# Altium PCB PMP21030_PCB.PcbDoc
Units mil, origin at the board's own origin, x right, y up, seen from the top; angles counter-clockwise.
Board outline 3700 x 1800 mil, 2 copper layers (Top Layer, Bottom Layer), stack 62 mil thick; 65 components, 29 nets, 169 pads, 54 vias.
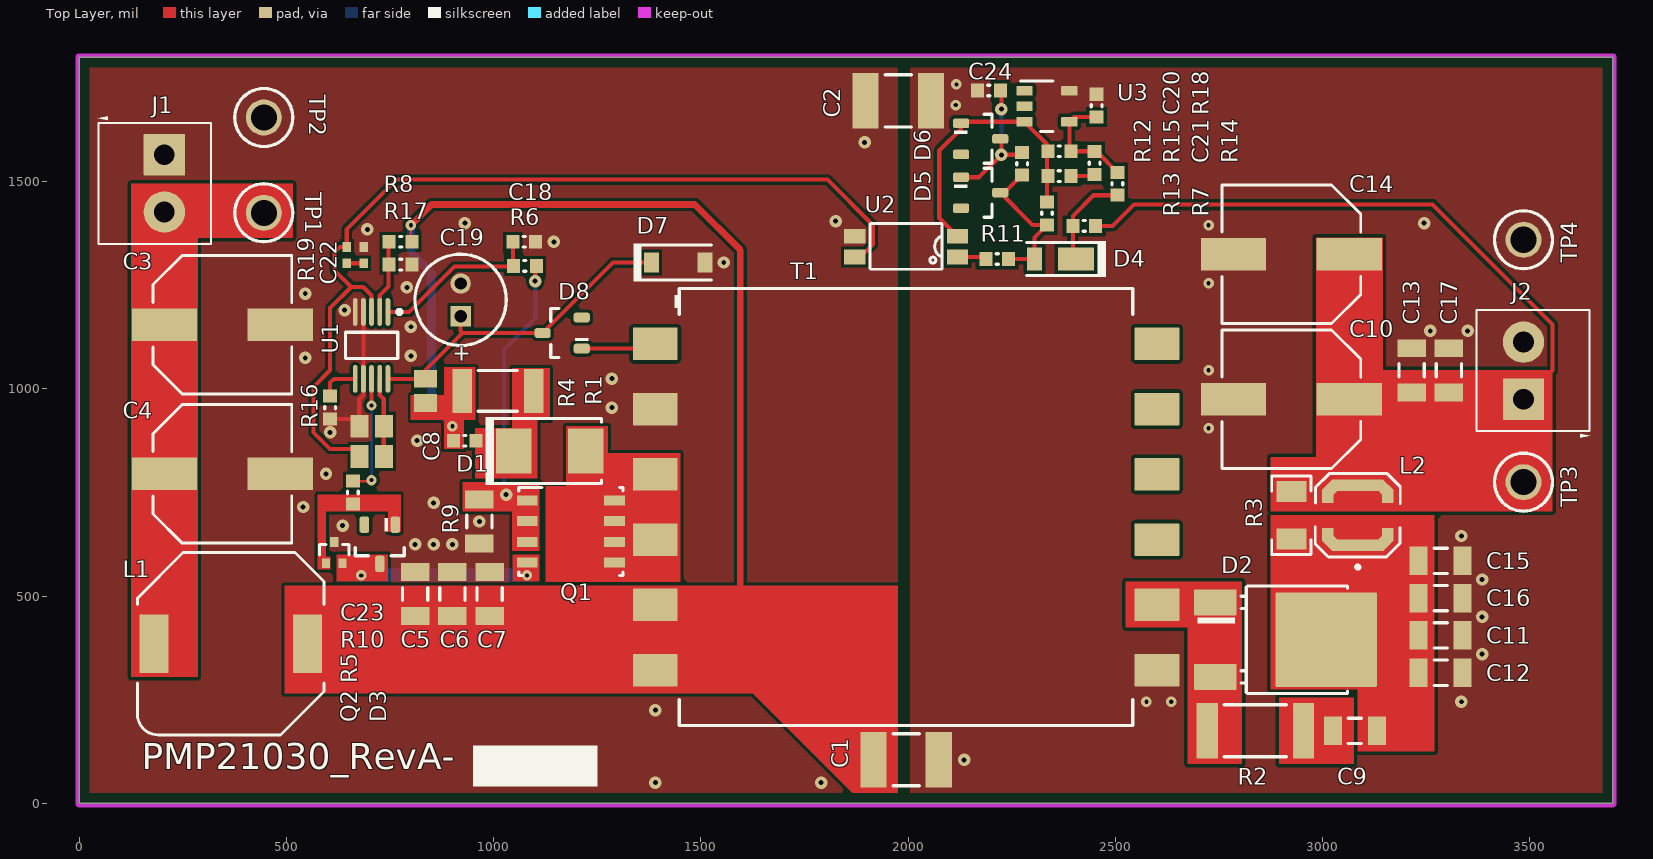
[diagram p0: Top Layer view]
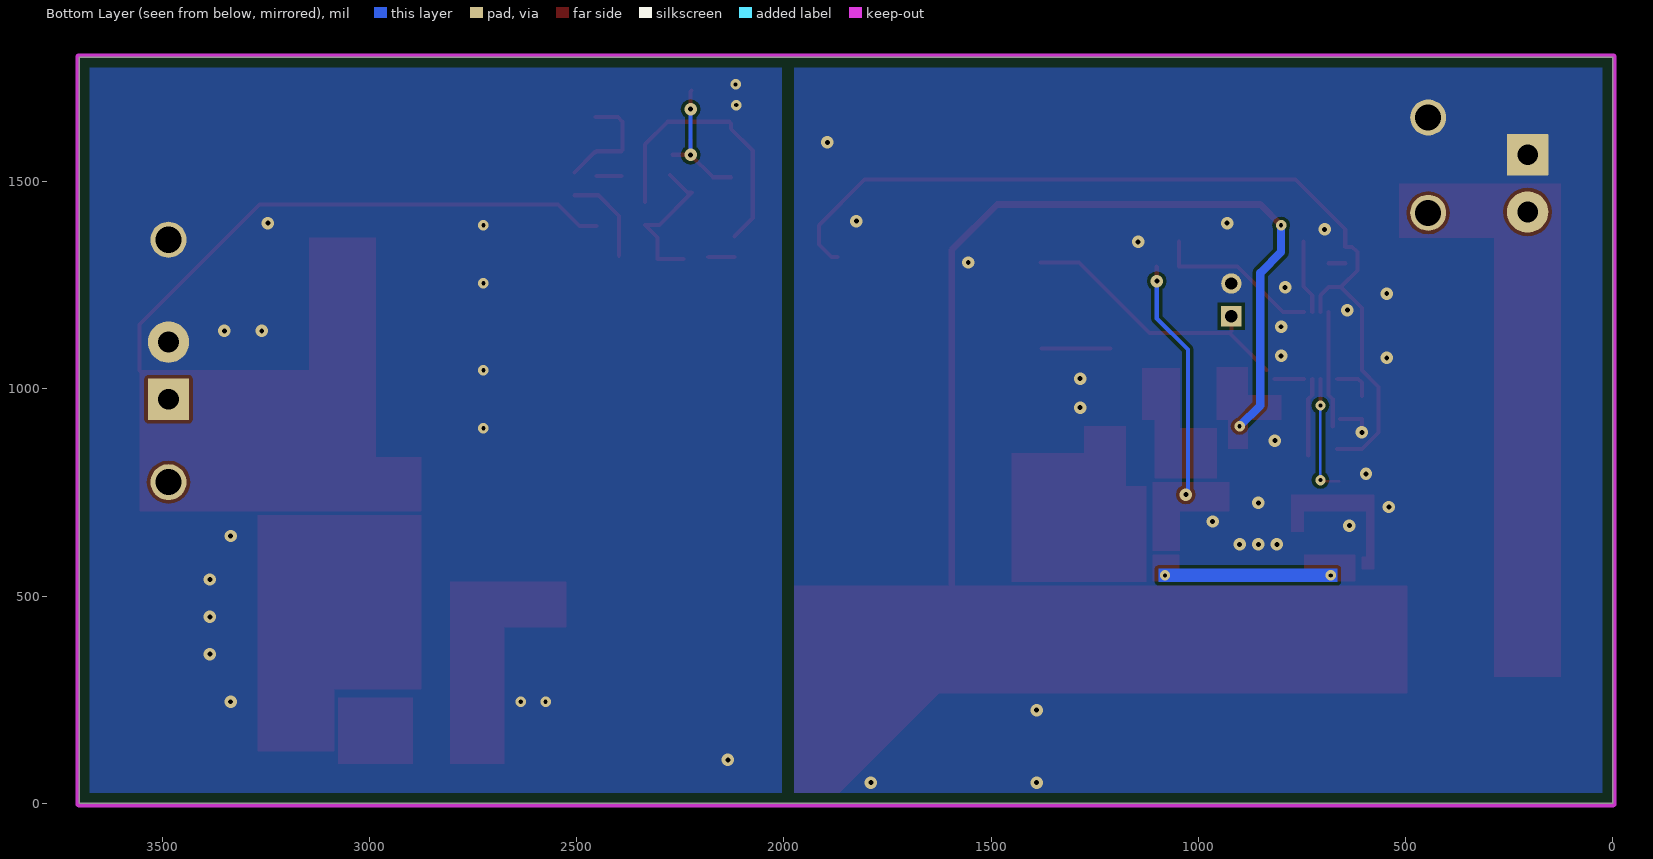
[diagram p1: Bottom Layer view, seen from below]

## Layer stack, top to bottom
Top Solder: solder mask 0.4, Solder Resist, Dk 3.5
Top Layer: signal copper 1.4
Dielectric1: core 59.2, FR-4, Dk 4.8
Bottom Layer: signal copper 1.4
Bottom Solder: solder mask 0.4, Solder Resist, Dk 3.5

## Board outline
0,0 3700,0 3700,1800 0,1800

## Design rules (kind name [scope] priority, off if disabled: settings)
AcuteAngle [All] p1: minimum=4.50000000000000E+0001 checktracksonly=FALSE
AssemblyTestPointUsage [All] p1: valid=2
BoardOutlineClearance BoardOutlineClearance_MountingHoles [OnCopper and InComponentClass('Mounting Holes')] p1: gap=25 ignorepadtopadclearanceinfootprint=FALSE
BoardOutlineClearance BoardOutlineClearance_Poly [OnCopper and InPoly] p2: gap=25 ignorepadtopadclearanceinfootprint=FALSE
BoardOutlineClearance [OnCopper and Not InComponentClass('Logo') and not InComponentClass('FiducialMark') and not InRegion(1000,500,4000,800)] p3: gap=25 ignorepadtopadclearanceinfootprint=FALSE
Clearance Clearance_Keepouts [((IsTrack Or IsArc) And Not InPoly) And IsFree and IsKeepOut vs ((IsTrack Or IsArc) And Not InPoly) And IsFree and IsKeepOut] p1: gap=10 ignorepadtopadclearanceinfootprint=FALSE
Clearance Clearance_Poly [InPolygon] p2: gap=8 ignorepadtopadclearanceinfootprint=FALSE except(0: Arc-Hole Track-Hole SMDPad-Hole THPad-Hole Via-Hole Fill-Hole Poly-Hole Region-Hole Text-Hole)
Clearance [All] p3: gap=7.87 ignorepadtopadclearanceinfootprint=FALSE except(0: Arc-Hole Track-Hole SMDPad-Hole THPad-Hole Via-Hole Fill-Hole Poly-Hole Region-Hole Text-Hole)
ComponentClearance ComponentClearance_MountingHoles_FiducialMarks [InComponentClass('Mounting Holes') vs InComponentClass('FiducialMark')] p1: gap=50 collisioncheckmode=3 verticalgap=10 showdistances=FALSE
ComponentClearance ComponentClearance_Shunt [InComponentClass('Header') vs InComponentClass('Shunt')] p2: gap=0 collisioncheckmode=3 verticalgap=0 showdistances=FALSE
ComponentClearance ComponentClearance_Logo [InComponentClass('Logo')] p3: gap=50 collisioncheckmode=3 verticalgap=10 showdistances=FALSE
ComponentClearance ComponentClearance_ScrewToNut [(HasFootprint('NY PMS 440 0025 PH')) vs (HasFootprint('Keystone_1902C'))] p4: gap=5 collisioncheckmode=3 verticalgap=10 showdistances=FALSE
ComponentClearance ComponentClearance_MountingHoles [InComponentClass('Mounting Holes')] p5: gap=250 collisioncheckmode=3 verticalgap=100000 showdistances=FALSE
ComponentClearance ComponentClearance_SmallPassives [HasFootprint('0201*') or HasFootprint('0402*') or HasFootprint('0508') or HasFootprint('0603*') or HasFootprint('0612') or HasFootprint('0805*') or HasFootprint('0815*') or HasFootprint('0830*') or HasFootprint('1206*') or HasFootprint('1210*') or HasFootprint('1808*') or HasFootprint('1812*') or HasFootprint('1825*') or HasFootprint('2010*') or HasFootprint('2220*') or HasFootprint('2225*') or HasFootprint('2512*') or HasFootprint('2728*') or HasFootprint('3518*') vs HasFootprint('0201*') or HasFootprint('0402*') or HasFootprint('0508') or HasFootprint('0603*') or HasFootprint('0612') or HasFootprint('0805*') or HasFootprint('0815*') or HasFootprint('0830*') or HasFootprint('1206*') or HasFootprint('1210*') or HasFootprint('1808*') or HasFootprint('1812*') or HasFootprint('1825*') or HasFootprint('2010*') or HasFootprint('2220*') or HasFootprint('2225*') or HasFootprint('2512*') or HasFootprint('2728*') or HasFootprint('3518*')] p6: gap=14.96 collisioncheckmode=3 verticalgap=10 showdistances=FALSE
ComponentClearance ComponentClearance_THtoSMT [IsThruComponent vs IsSMTComponent] p7: gap=15 collisioncheckmode=3 verticalgap=30 showdistances=FALSE
ComponentClearance ComponentClearance_THtoTH [IsThruComponent vs IsThruComponent] p8: gap=15 collisioncheckmode=3 verticalgap=30 showdistances=FALSE
ComponentClearance [All] p9: gap=15 collisioncheckmode=3 verticalgap=10 showdistances=FALSE
DiffPairsRouting [All] p1: maxlimit=100 minlimit=10 mostfreqgap=10 toplayer_minwidth=15 toplayer_maxwidth=15 toplayer_prefwidth=15 bottomlayer_minwidth=15 bottomlayer_maxwidth=15 bottomlayer_prefwidth=15 maxuncoupledlength=1000
FabricationTestPointUsage TestPointUsage [All] p1: valid=2 allowmultiple=FALSE
FabricationTestpoint Testpoint [All] p1: side=3 testpointundercomponent=TRUE minsize=40 maxsize=100 preferedsize=60 minholesize=0 maxholesize=40 preferedholesize=32 testpointgrid=1 allowsidetop=TRUE allowsidebottom=TRUE usegrid=TRUE gridtolerance=0.01
FanoutControl Fanout_LCC [IsLCC] p1: bgadir=Out bgaviamode=Centered fanoutstyle=Auto fanoutdirection=Alternating viagrid=1 // Fanout_LCC (Default Rule)
FanoutControl Fanout_BGA [IsBGA] p2: bgadir=Out bgaviamode=Centered fanoutstyle=Auto fanoutdirection=Alternating viagrid=1 // Fanout_BGA (Default Rule)
FanoutControl Fanout_Default [All] p4: bgadir=Out bgaviamode=Centered fanoutstyle=Auto fanoutdirection=Alternating viagrid=1 // Fanout_Default (Default Rule)
FanoutControl Fanout_Small [(CompPinCount < 5)] p5: bgadir=Out bgaviamode=Centered fanoutstyle=Auto fanoutdirection=OutThenIn viagrid=1 // Fanout_Small (Default Rule)
HoleSize [All] p1: absolutevalues=TRUE maxlimit=251 minlimit=7.87 maxpercent=80.000 minpercent=20.000
MinimumAnnularRing MinimumAnnularRing_ThermalPadVias [IsVia and InAnyComponent] p1: minimumring=5.91
MinimumAnnularRing [All] p2: minimumring=7
MinimumSolderMaskSliver MinimumSolderMaskSliver_Logo [InComponentClass('Logo') vs InComponentClass('Logo')] p1: minsoldermaskwidth=0.7
MinimumSolderMaskSliver [All] p2: minsoldermaskwidth=0.7
PlaneConnect [All] p1: planeconnectstyle=Direct reliefexpansion=10 reliefentries=4 reliefconductorwidth=10 reliefairgap=10
PolygonConnect [All] p1: connectstyle=Direct reliefconductorwidth=10 reliefentries=4 polygonreliefangle="90 Angle" airgapwidth=10
RoutingVias ThermalPadVias [IsVia and InAnyComponent] p1: holewidth=7.87 width=19.68 viastyle="Through Hole" minholewidth=7.87 minwidth=19.68 maxholewidth=12.99 maxwidth=23.62
RoutingVias [All] p2: holewidth=16 width=34 viastyle="Through Hole" minholewidth=7.87 minwidth=25 maxholewidth=40 maxwidth=65
SilkToBoardRegionClearance [Not ((IsComment or IsDesignator) And (Hide <> 'False')) and not InRegion(1000,500,4000,800)] p1:
SilkToSilkClearance SilkToSilkClearance_Pb-FreeLogo [(HasFootprint('Pb-Free_Overlay_Medium') OR HasFootprint('Pb-Free_Overlay_Small')) vs (HasFootprint('Pb-Free_Overlay_Medium') OR HasFootprint('Pb-Free_Overlay_Small'))] p1: silktosilkclearance=0
SilkToSilkClearance [All] p2: silktosilkclearance=4
SilkToSolderMaskClearance SilkToComponentPadClearance [IsPad and InAnycomponent] p1: minsilkscreentomaskgap=5 clearancetoexposedcopper=TRUE
SilkToSolderMaskClearance "Silk to Solder Mask Opening" [All] p2: minsilkscreentomaskgap=4 clearancetoexposedcopper=FALSE
SolderMaskExpansion [All] p1: expansion=1.97
Width [All] p1: maxlimit=100 minlimit=6 preferedwidth=10 checkconnectedcopper=TRUE
15 further rules are at their usual default settings.

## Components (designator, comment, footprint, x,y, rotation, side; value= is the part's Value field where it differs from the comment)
C1 "C4532X7R3D222K130KA" 1812 1995,105 r180 top value=2200pF
C2 "C4532X7R3D222K130KA" 1812 1976.26,1695 r180 top value=2200pF
C3 "EEE-FK1J470P" SM_RADIAL_F 345,1155 r0 top value=47uF
C4 "EEE-FK1J470P" SM_RADIAL_F 345,795 r0 top value=47uF
C5 "C3216X7S2A225K160AB" 1206l 810,505 r90 top value=2.2uF
C6 "C3216X7S2A225K160AB" 1206l 900,505 r90 top value=2.2uF
C7 "C3216X7S2A225K160AB" 1206l 990,505 r90 top value=2.2uF
C8 "GCJ188R72A104KA01D" 0603L 930,875 r0 top value=0.1uF
C9 "GRM31A7U2J221JW31D" 1206L 3077.91,175 r180 top value=220pF
C10 "EEE-FK1J470P" SM_RADIAL_F 2925,975 r180 top value=47uF
C11 "C3216X7S2A225K160AB" 1206l 3285,405 r0 top value=2.2uF
C12 "C3216X7S2A225K160AB" 1206l 3285,315 r0 top value=2.2uF
C13 "C3216X7S2A225K160AB" 1206l 3215,1045 r90 top value=2.2uF
C14 "EEE-FK1J470P" SM_RADIAL_F 2925,1325 r180 top value=47uF
C15 "C3216X7S2A225K160AB" 1206l 3285,585 r0 top value=2.2uF
C16 "C3216X7S2A225K160AB" 1206l 3285,495 r0 top value=2.2uF
C17 "GRM31CR72D104KW03L" 1206l 3305,1045 r90 top value=0.1uF
C18 "GRM1885C2A101JA01D" 0603L 1073.5,1355 r0 top value=100pF
C19 "EKMG101ELL1R0ME11D" Chemi-Con_500x1100 920,1215 r90 top value=1uF
C20 "GCM188R71H472KA37D" 0603L 2364.96,1573.5 r180 top value=4700pF
C21 "C1608X7R1E104K080AA" 0603L 2450,1545 r270 top value=0.1uF
C22 "GRM155R61E475ME15" 0402L 686,1323 r90 top value=4.7uF
C23 "GRM219R71E105KA88D" 0805L 705,910 r180 top value=1uF
C24 "GCM188R71E105KA64D" 0603L 2195,1720 r180 top value=1uF
D1 "ES2D-13-F" SMB 1135,850 r0 top value=200V
D2 "MURD320T4G" DPAK 2875,395 r0 top value=200V
D3 "BAS16LT1G" SOT-23 725,625 r270 top value=100V
D4 "DFLZ24-7" PowerDI123 2354.96,1313.5 r180 top value=24V
D5 "BAS16LT1G" SOT-23 2174.96,1473.5 r0 top value=100V
D6 "BAS16LT1G" SOT-23 2174.96,1603.5 r0 top value=100V
D7 "MMSZ4717T1G" SOD-123 1445,1305 r0 top value=43V
D8 "BAS16LT1G" SOT-23 1165,1135 r180 top value=100V
J1 "ED555/2DS" TERM_BLK_ED555-2DS 205,1565 r270 top
J2 "ED555/2DS" TERM_BLK_ED555-2DS 3485,975 r90 top
L1 "MSS1048-103MLB" MSS1048 365,385 r0 top value=10uH
L2 "LPS4018-332MLB" LPS4018 3085,695 r90 top value=3.3uH
Q1 "FDMS86200" TRANS_Fairchild_PQFN08A 1186,656 r0 top value=150V
Q2 "MMBT3906TT1G" SOT-416 615,605 r90 top value="40 V"
R1 "CRCW201051K0JNEF" 2010L 1010,995 r180 top value=51k
R2 "CRCW251251R0JNEG" 2512 2837.91,175 r0 top value=51
R3 "CRCW12061R00JNEA" 1206 2925,695 r90 top value=1.0
R4 "CRCW08052K00JNEA" 0805L 835,995 r270 top value=2.0k
R5 "CRCW06034R70JNEA" 0603L 660,750 r270 top value=4.7
R6 "CRCW06032K05FKEA" 0603L 1075,1297 r0 top value=2.05k
R7 "CRCW06030000Z0EA" 0603L 2424.96,1393.5 r0 top value=0
R8 "CRCW0603100KFKEA" 0603L 775,1355 r0 top value=100k
R9 "WSLP1206R0200FEA" 1206L 965,680 r90 top value=0.02
R10 "CRCW08054K70JNEA" 0805L 705,837 r180 top value=4.7k
R11 "CRCW06034K99FKEA" 0603L 2214.96,1313.5 r0 top value=4.99k
R12 "CRCW060310K0FKEA" 0603L 2274.96,1543.5 r270 top value=10.0k
R13 "CRCW060310K0FKEA" 0603L 2334.96,1423.5 r270 top value=10.0k
R14 "CRCW060349K9FKEA" 0603L 2505,1495 r270 top value=49.9k
R15 "CRCW060349K9FKEA" 0603L 2364.96,1513.5 r180 top value=49.9k
R16 "CRCW0603140KFKEA" 0603L 605,955 r270 top value=140k
R17 "CRCW06039K31FKEA" 0603L 775,1300 r180 top value=9.31k
R18 "CRCW06032K74FKEA" 0603L 2454.96,1683.5 r270 top value=2.74k
R19 "CRCW0402499RFKED" 0402L 645,1323 r90 top value=499
T1 "GA3136-BL" Coilcraft_GA3136-BL 1995,715 r0 top value=35uH
TP1 "5005" Keystone5005 445,1425 r90 top
TP2 "5006" Keystone5006 445,1655 r90 top
TP3 "5005" Keystone5005 3485,775 r90 top
TP4 "5006" Keystone5006 3485,1360 r90 top
U1 "LM3481MM/NOPB" MUB10A_N 705,1105 r270 top
U2 "TCMT1107" SOP-4 1994.96,1343.5 r180 top
U3 "TL431AIDBVRA" DBV0005A_N 2334.96,1682.01 r0 top

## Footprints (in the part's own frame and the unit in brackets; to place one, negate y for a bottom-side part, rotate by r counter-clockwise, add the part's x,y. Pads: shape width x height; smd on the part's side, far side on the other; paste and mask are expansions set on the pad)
0402L [mm] "0402 from SM-752 data"
  rect 0.6x0.5 smd: 1(-0.5,0) 2(0.5,0)
  body extent -0.55,-0.3 0.55,0.3, height 0.6
0603L [mm] "0603 from SM-752 data"
  rect 0.8x0.85 smd: 1(-0.7,0) 2(0.7,0)
  silkscreen extent -0.07,-0.33 0.07,0.33, body extent -0.87,-0.47 0.87,0.47, height 1
0805L [mm] "0805 from SM-752 data"
  rect 1.1x1.4 smd: 1(-0.75,0) 2(0.75,0)
  body extent -1.1,-0.72 1.1,0.72, height 1.45
1206 [mm] "1206 from SM-752 data"
  rect 1.3x1.85 smd: 1(-1.45,0) 2(1.45,0)
  silkscreen extent -2.4,-1.21 2.4,1.21, body extent -1.7,-0.9 1.7,0.9, height 1.35
1206l [mm] "1206 from SM-752 data"
  rect 1.1x1.75 smd: 1(-1.35,0) 2(1.35,0)
  silkscreen extent -0.4,-0.77 0.4,0.77, body extent -1.7,-0.9 1.7,0.9, height 1.35
1206L [mm] "1206 from SM-752 data"
  rect 1.1x1.75 smd: 1(-1.35,0) 2(1.35,0)
  silkscreen extent -0.4,-0.77 0.4,0.77, body extent -1.7,-0.9 1.7,0.9, height 1.35
1812 [mm]
  rect 1.6x3.4 smd: 1(-2,0) 2(2,0)
  silkscreen extent -0.8,-1.6 0.8,1.6, body extent -2.4,-1.7 2.4,1.7, height 1.35
2010L [mm]
  rect 1.2x2.7 smd: 1(-2.2,0) 2(2.2,0)
  silkscreen extent -1.2,-1.25 1.2,1.25, body extent -2.73,-1.45 2.73,1.45, height 1.66
2512 [mm] "Chip Resistor, Body 6.3x3.2mm, IPC Medium Density"
  rect 1.3x3.4 smd: 1(-2.95,0) 2(2.95,0)
  silkscreen extent -1.9,-1.6 1.9,1.6, body extent -3.22,-1.67 3.22,1.67, height 0.71
Chemi-Con_500x1100 [mm] "TH, 2-Leads, Dia 5mm, Lead Sapcing 2mm"
  rect 1.25x1.25 hole 0.75: 1(-1,0)
  round 1.25 hole 0.75: 2(1,0)
  silkscreen extent -2.8,-2.8 2.8,2.8, body extent -2.75,-2.75 2.75,2.75, height 12.5
Coilcraft_GA3136-BL [mm] "SMD, 12-Leads, Body 26x26.75mm"
  rrect5% 2.75x2 smd: 1(-15.375,10) 2(-15.375,6) 3(-15.375,2) 4(-15.375,-2) 5(-15.375,-6) 6(-15.375,-10) 7(15.375,-10) 8(15.375,-6) 9(15.375,-2) 10(15.375,2) 11(15.375,6) 12(15.375,10)
  silkscreen extent -14.2,-13.4 13.9,13.4, body extent -16.33,-13.38 16.33,13.37, height 14
DBV0005A_N [mm] "SOT23, 5-Leads, Body 2.9x1.6mm, Pitch 0.95mm, Lead Span 2.8mm, IPC Medium Density"
  rrect17% 1x0.6 smd: 1(-1.375,0.95) 2(-1.375,0) 3(-1.375,-0.95) 4(1.375,-0.95) 5(1.375,0.95)
  silkscreen extent -1.63,-1.55 0.38,1.55, body extent -1.42,-1.46 1.42,1.46, height 1.09
DPAK [mm] "D-PAK, 3-Pads, Body 6.22x6.73mm (max), TO-252AA using nominal STEP model"
  rrect6% 2.6x1.6 smd: 1(-3.4,2.28) 3(-3.4,-2.28)
  rrect2% 6.2x5.8 smd paste-2.9: 4(3.4,0)
  silkscreen extent -4.5,-3.3 4.7,3.28, body extent -3.86,-3.29 5.84,3.29, height 2.48
Keystone5005 [mil] "Keystone Compact loops"
  round 87 hole 63: 1(0,0)
  silkscreen extent -70,-70 70,70, body extent -63,-63 62,63, height 225
Keystone5006 [mil] "Keystone Compact loops"
  round 87 hole 63: 1(0,0)
  silkscreen extent -70,-70 70,70, body extent -63,-63 62,63, height 225
LPS4018 [mil]
  rect 28x123 smd: 1(-72.5,0) 2(72.5,0)
  rect 35.5x28 smd rot 45: 1(-64,64) 2(64.5,-63.5)
  rect 35.5x28 smd rot 135: 1(-64,-64) 2(64,64)
  rect 31.5x28 smd: 1(-46,72.5) 1(-46,-72.5) 2(46,72.5) 2(46,-72.5)
  silkscreen extent -129,-102 100,102, body extent -81,-81 81,81, height 71
MSS1048 [mm] "Coilcraft recommended land pattern Document 462-2 Revised 06/09/09"
  rect 1.78x3.56 smd: 1(-4.7,0) 2(4.7,0)
  silkscreen extent -5.71,-5.59 5.71,5.59, body extent -5.15,-5.1 5.15,5.1, height 5.12
MUB10A_N [mm] "TSSOP, 10-Leads, Body 3x3mm, Pitch 0.5mm, IPC Medium Density"
  oval 1.7x0.3 smd: 1(-2.05,1) 2(-2.05,0.5) 3(-2.05,0) 4(-2.05,-0.5) 5(-2.05,-1) 6(2.05,-1) 7(2.05,-0.5) 8(2.05,0) 9(2.05,0.5) 10(2.05,1)
  silkscreen extent -2.17,-1.6 0.8,1.83, body extent -1.6,-1.6 1.6,1.6, height 1.09
PowerDI123 [mm] "Diodes Inc recommended land pattern, document number DS30628 Rev. 6-2"
  rect 2.2x1.4 smd: 1(-1.275,0)
  rect 0.9x1.4 smd: 2(1.275,0)
  silkscreen extent -3.1,-1.09 1.76,1.09, body extent -2.38,-0.97 1.52,0.96, height 1
SM_RADIAL_F [mm] "8 x 10.2mm:  Panasonic F"
  rect 4x2 smd: 1(-3.55,0) 2(3.55,0)
  silkscreen extent -4.25,-4.25 4.25,4.25, body extent -4.25,-4.25 4.25,4.25, height 10.5
SMB [mil] "Molded Diode, 2-Leads, Body 5.4x3.6mm, IPC Medium Density, based on OnSemi component dimensions"
  rect 85x107.99 smd: 1(-87.01,0) 2(87.01,0)
  silkscreen extent -155,-82 125,82, body extent -106,-71 106,71, height 91
SOD-123 [mm] "On Semi recommended land pattern"
  rect 0.915x1.22 smd: 1(-1.637,0) 2(1.637,0)
  silkscreen extent -2.74,-1.17 2.03,1.17, body extent -1.93,-0.9 1.93,0.9, height 1.35
SOP-4 [mm] "Vishay Half Pitch Mini-Flat Package"
  rect 1.3x0.9 smd: 1(-3.15,0.635) 2(-3.15,-0.635) 3(3.15,-0.635) 4(3.15,0.635)
  silkscreen extent -2.2,-1.41 2.2,1.39, body extent -3.5,-1.4 3.5,1.4, height 2.12
SOT-23 [mm] "SOT23, 3-Leads, Body 2.9x1.3mm, Pitch 0.95mm, Lead Span 2.5mm, IPC Medium Density"
  rrect50% 1x0.6 smd: 1(-1.2,0.95) 2(-1.2,-0.95) 3(1.2,0)
  silkscreen extent -1.63,-1.5 0.7,1.5, body extent -1.16,-1.45 1.21,1.45, height 1
SOT-416 [mm] "NXP recommended footprint."
  rect 0.6x0.5 smd: 1(-0.65,0.5) 2(-0.65,-0.5) 3(0.65,0)
  silkscreen extent -0.13,-0.9 0.5,0.9, body extent -0.8,-0.9 0.8,0.9, height 0.82
TERM_BLK_ED555-2DS [mil]
  rrect4% 100x100 hole 50: 1(0,0)
  round 100 hole 50: 2(138,0)
  silkscreen extent -93,-161 215,113, body extent -69,-150 207,106, height 323
TRANS_Fairchild_PQFN08A [mm] "Fairchild PQFN08A recommended land pattern"
  rect 1.27x0.61 smd: 1(-2.67,1.905) 2(-2.67,0.635) 3(-2.67,-0.635) 4(-2.67,-1.905) 5(2.67,-1.905) 6(2.67,-0.635) 7(2.67,0.635) 8(2.67,1.905)
  Top Layer region: -1.215,-2.55 2.535,-2.55 2.535,2.55 -1.215,2.55
  silkscreen extent -3.2,-2.7 3.2,2.7, body extent -3.05,-2.55 3.05,2.55, height 1.11

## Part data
C1 C2: "CAP, CERM, 2200 pF, 2000 V,+/- 10%, X7R, 1812", Cap_Case=1812, Manufacturer=TDK, Supplier Part Number 1=445-2389-1-ND, TempCo=X7R, Tolerance_%=10, Value2=2000V, ValueDisplayed=2200pF
C3 C4 C10 C14: "CAP, AL, 47 µF, 63 V, +/- 20%, 0.65 ohm, AEC-Q200 Grade 2, SMD", Cap_Case=F, Manufacturer=Panasonic, Supplier Part Number 1=PCE3823CT-ND, Tolerance_%=20, Value1="0.65 ohm", Value2=63V, ValueDisplayed=47µF
C5 C6 C7 C11 C12 C13 C15 C16: "CAP, CERM, 2.2 µF, 100 V,+/- 10%, X7S, 1206", Cap_Case=1206, Manufacturer=TDK, Supplier Part Number 1=445-5207-1-ND, TempCo=X7S, Tolerance_%=10, Value1="0.005718 ohm", Value2=100V, ValueDisplayed=2.2µF
C8: "CAP, CERM, 0.1 µF, 100 V,+/- 10%, X7R, AEC-Q200 Grade 1, 0603", Cap_Case=0603, Manufacturer=MuRata, Supplier Part Number 1=490-13420-1-ND, TempCo=X7R, Tolerance_%=10, Value2=100V, ValueDisplayed=0.1µF
C9: "CAP, CERM, 220 pF, 630 V,+/- 5%, U2J, 1206", Cap_Case=1206, Manufacturer=MuRata, Supplier Part Number 1=490-4292-1-ND, TempCo=U2J, Tolerance_%=5, Value2=630V, ValueDisplayed=220pF
C17: "CAP, CERM, 0.1 µF, 200 V,+/- 10%, X7R, 1206", Cap_Case=1206, Manufacturer=MuRata, Supplier Part Number 1=490-13379-1-ND, TempCo=X7R, Tolerance_%=10, Value2=200V, ValueDisplayed=0.1µF
C18: "CAP, CERM, 100 pF, 100 V,+/- 5%, C0G/NP0, 0603", Cap_Case=0603, Manufacturer=MuRata, Supplier Part Number 1=490-1351-1-ND, TempCo=C0G/NP0, Tolerance_%=5, Value2=100V, ValueDisplayed=100pF
C19: "CAP, AL, 1 µF, 100 V, +/- 20%, TH", Cap_Case=5x11mm, Manufacturer=Chemi-Con, Supplier Part Number 1=565-1360-ND, Tolerance_%=20, Value2=100V, ValueDisplayed=1µF
C20: "CAP, CERM, 4700 pF, 50 V,+/- 10%, X7R, AEC-Q200 Grade 1, 0603", Cap_Case=0603, Manufacturer=MuRata, Supplier Part Number 1=490-4932-1-ND, TempCo=X7R, Tolerance_%=10, Value2=50V, ValueDisplayed=4700pF
C21: "CAP, CERM, 0.1 µF, 25 V,+/- 10%, X7R, 0603", Cap_Case=0603, Manufacturer=TDK, Supplier Part Number 1=445-1316-1-ND, TempCo=X7R, Tolerance_%=10, Value2=25V, ValueDisplayed=0.1µF
C22: "CAP, CERM, 4.7 µF, 25 V,+/- 20%, X5R, 0402", Cap_Case=0402, Manufacturer=MuRata, TempCo=X5R, Tolerance_%=20, Value2=25V, ValueDisplayed=4.7µF
C23: "CAP, CERM, 1 µF, 25 V,+/- 10%, X7R, 0805", Cap_Case=0805, Manufacturer=MuRata, Supplier Part Number 1=GRM219R71E105KA88D-ND, TempCo=X7R, Tolerance_%=10, Value2=25V, ValueDisplayed=1µF
C24: "CAP, CERM, 1 µF, 25 V,+/- 10%, X7R, AEC-Q200 Grade 1, 0603", Cap_Case=0603, Manufacturer=MuRata, Supplier Part Number 1=490-10673-1-ND, TempCo=X7R, Tolerance_%=10, Value2=25V, ValueDisplayed=1µF
D1: "Diode, Ultrafast, 200 V, 2 A, SMB", Manufacturer="Diodes Inc.", Supplier Part Number 1=ES2D-FDICT-ND, Value1=2A, Value2=0.92V
D2: library part CMP-0074782-1, "Diode, Ultrafast, 200 V, 3 A, AEC-Q101, DPAK", Manufacturer="ON Semiconductor", Supplier Part Number 1=MURD320T4GOSCT-ND, Value1=3A, Value2=0.95V
D3 D5 D6 D8: "Diode, Switching, 100 V, 0.2 A, SOT-23", Manufacturer="ON Semiconductor", Supplier Part Number 1=BAS16LT1GOSCT-ND, Value1=0.2A, Value2=1.25V
D4: "Diode, Zener, 24 V, 1 W, PowerDI123", Manufacturer="Diodes Inc.", Power_W=1, Supplier Part Number 1=DFLZ24DICT-ND, Value1=1W
D7: library part CMP-0005748-2, "Diode, Zener, 43 V, 500 mW, SOD-123", Manufacturer="ON Semiconductor", Power_W=500mW, Supplier Part Number 1=MMSZ4717T1GOSCT-ND, Value1=0.5W
J1 J2: "Terminal Block, 3.5mm Pitch, 2x1, TH", Color=Grey, Current_A=6, Manufacturer="On-Shore Technology", Supplier Part Number 1=ED1514-ND, Voltage_V=150
L1: "Inductor, Shielded Drum Core, Ferrite, 10 µH, 4.32 A, 0.03 ohm, SMD", Manufacturer=Coilcraft, Value1="0.03 ohm", Value2=4.32A, ValueDisplayed=10µH
L2: "Inductor, Shielded Drum Core, Ferrite, 3.3 µH, 1.9 A, 0.08 ohm, SMD", Manufacturer=Coilcraft, Value1="0.08 ohm", Value2=1.9A, ValueDisplayed=3.3µH
Q1: "MOSFET, N-CH, 150 V, 35 A, PQFN08A", Alternate Manufacturer=None, Manufacturer="Fairchild Semiconductor", Supplier Part Number 1=FDMS86200CT-ND, Value1="? ohm", Value2="33 nC"
Q2: library part "MMBT3906TT1G, ON Semiconductor", "Transistor, PNP, 40 V, 0.2 A, SOT-416", Manufacturer="ON Semiconductor", Supplier Part Number 1=MMBT3906TT1GOSCT-ND, Value1="0.2 A", Value2=300
R1: "RES, 51 k, 5%, 0.75 W, AEC-Q200 Grade 0, 2010", Manufacturer=Vishay-Dale, Power_W=0.75, Supplier Part Number 1=541-51KWCT-ND, TempCo="200 ppm/C", Tolerance_%=5, Value1=5%, Value2=0.75W, Value_Code=51k0, ValueDisplayed=51k
R2: "RES, 51, 5%, 1 W, AEC-Q200 Grade 0, 2512", Manufacturer=Vishay-Dale, Power_W=1, Supplier Part Number 1=541-51XCT-ND, TempCo="200 ppm/C", Tolerance_%=5, Value1=5%, Value2=1W, Value_Code=51R0, ValueDisplayed=51
R3: "RES, 1.0, 5%, 0.25 W, 1206", Manufacturer=Vishay-Dale, Power_W=0.25, Supplier Part Number 1=541-1.0ECT-ND, TempCo="200 ppm/C", Tolerance_%=5, Value1=5%, Value2=0.25W, Value_Code=1R00, ValueDisplayed=1.0
R4: "RES, 2.0 k, 5%, 0.125 W, 0805", Manufacturer=Vishay-Dale, Power_W=0.125, Supplier Part Number 1=541-2.0KACT-ND, TempCo="200 ppm/C", Tolerance_%=5, Value1=5%, Value2=0.125W, Value_Code=2k00, ValueDisplayed=2.0k
R5: "RES, 4.7, 5%, 0.1 W, 0603", Manufacturer=Vishay-Dale, Power_W=0.1, Supplier Part Number 1=541-4.7GCT-ND, TempCo="200 ppm/C", Tolerance_%=5, Value1=5%, Value2=0.1W, Value_Code=4R70, ValueDisplayed=4.7
R6: "RES, 2.05 k, 1%, 0.1 W, 0603", Manufacturer=Vishay-Dale, Power_W=0.1, Supplier Part Number 1=541-2.05KHCT-ND, TempCo="100 ppm/C", Tolerance_%=1, Value1=1%, Value2=0.1W, Value_Code=2k05, ValueDisplayed=2.05k
R7: "RES, 0, 5%, 0.1 W, 0603", Manufacturer=Vishay-Dale, Power_W=0.1, Supplier Part Number 1=541-0.0GCT-ND, TempCo="200 ppm/C", Tolerance_%=5, Value1=5%, Value2=0.1W, Value_Code=0000, ValueDisplayed=0
R8: "RES, 100 k, 1%, 0.1 W, 0603", Manufacturer=Vishay-Dale, Power_W=0.1, Supplier Part Number 1=541-100KHCT-ND, TempCo="100 ppm/C", Tolerance_%=1, Value1=1%, Value2=0.1W, Value_Code=100k
R9: "RES, 0.02, 1%, 1 W, 1206", Manufacturer=Vishay-Dale, Power_W=1, Supplier Part Number 1=WSLP-.02CT-ND, TempCo="75 ppm/C", Value1=1%, Value2=1W, Value_Code=R020, ValueDisplayed=0.02
R10: "RES, 4.7 k, 5%, 0.125 W, 0805", Manufacturer=Vishay-Dale, Power_W=0.125, Supplier Part Number 1=541-4.7KACT-ND, TempCo="200 ppm/C", Tolerance_%=5, Value1=5%, Value2=0.125W, Value_Code=4k70, ValueDisplayed=4.7k
R11: "RES, 4.99 k, 1%, 0.1 W, 0603", Manufacturer=Vishay-Dale, Power_W=0.1, Supplier Part Number 1=541-4.99KHCT-ND, TempCo="100 ppm/C", Tolerance_%=1, Value1=1%, Value2=0.1W, Value_Code=4k99, ValueDisplayed=4.99k
R12 R13: "RES, 10.0 k, 1%, 0.1 W, 0603", Manufacturer=Vishay-Dale, Power_W=0.1, Supplier Part Number 1=541-10.0KHCT-ND, TempCo="100 ppm/C", Tolerance_%=1, Value1=1%, Value2=0.1W, Value_Code=10k0, ValueDisplayed=10.0k
R14 R15: "RES, 49.9 k, 1%, 0.1 W, 0603", Manufacturer=Vishay-Dale, Power_W=0.1, Supplier Part Number 1=541-49.9KHCT-ND, TempCo="100 ppm/C", Tolerance_%=1, Value1=1%, Value2=0.1W, Value_Code=49k9, ValueDisplayed=49.9k
R16: "RES, 140 k, 1%, 0.1 W, 0603", Manufacturer=Vishay-Dale, Power_W=0.1, Supplier Part Number 1=541-140KHCT-ND, TempCo="100 ppm/C", Tolerance_%=1, Value1=1%, Value2=0.1W, Value_Code=140k
R17: "RES, 9.31 k, 1%, 0.1 W, 0603", Manufacturer=Vishay-Dale, Power_W=0.1, Supplier Part Number 1=541-9.31KHCT-ND, TempCo="100 ppm/C", Tolerance_%=1, Value1=1%, Value2=0.1W, Value_Code=9k31, ValueDisplayed=9.31k
R18: "RES, 2.74 k, 1%, 0.1 W, 0603", Manufacturer=Vishay-Dale, Power_W=0.1, Supplier Part Number 1=541-2.74KHCT-ND, TempCo="100 ppm/C", Tolerance_%=1, Value1=1%, Value2=0.1W, Value_Code=2k74, ValueDisplayed=2.74k
R19: "RES, 499, 1%, 0.063 W, 0402", Manufacturer=Vishay-Dale, Power_W=0.063, Supplier Part Number 1=541-499LCT-ND, TempCo="100 ppm/C", Tolerance_%=1, Value1=1%, Value2=0.063W, Value_Code=499R, ValueDisplayed=499
T1: library part CMP-0074777-1, "Transformer, Flyback, 35 uH, SMD", Manufacturer=Coilcraft, Supplier Part Number 1=994-GA3136-BL, ValueDisplayed=35µH
TP1 TP3: library part CMP-0055142-1, "Test Point, Compact, Red, TH", Color=Red, Manufacturer=Keystone, Supplier Part Number 1=36-5005-ND
TP2 TP4: "Test Point, Compact, Black, TH", Color=Black, Manufacturer=Keystone, Supplier Part Number 1=36-5006-ND
U1: "High Efficiency Low-Side N-Channel Controller for Switching Regulators, 10-pin MSOP, Pb-Free", Manufacturer="Texas Instruments", PackageTopMarking=ZXTT*SJPB, PowerWise=N, Supplier Part Number 1=LM3481MMTR-ND
U2: "Optocoupler, 3.75 kV, 80-160% CTR, SMT", Manufacturer=Vishay-Semiconductor, Supplier Part Number 1=TCMT1107CT-ND, Voltage_Isolation_Vrms=3750V
U3: library part TL431AIDBVR, "Adjustable Precision Shunt Regulator, 34 ppm / degC, 100 mA, -40 to 85 degC, 5-pin SOT-23 (DBV), Green (RoHS & no Sb/Br)", Alternate Manufacturer="Texas Instruments", Alternate PartNumber=Equivalent, Rating=Catalog, Supplier Part Number 1=296-15237-2-ND, Temp Coeff(Max)(ppm/ degree C)=92, Temp Coeff(Typ)(ppm/ degree C)=34

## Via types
v1: diameter 30, hole 12, Top Layer to Bottom Layer, tented both sides, 38 vias
v2: diameter 25, hole 10, Top Layer to Bottom Layer, tented both sides, 14 vias
v3: diameter 30, hole 12, Top Layer to Bottom Layer, 2 vias

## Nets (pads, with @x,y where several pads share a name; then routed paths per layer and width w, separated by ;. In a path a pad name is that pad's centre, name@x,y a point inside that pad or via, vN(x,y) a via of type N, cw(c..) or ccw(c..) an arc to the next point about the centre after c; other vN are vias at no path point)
GND: C1.1 C2.1 C10.2 C11.2 C12.2 C13.2 C14.2 C15.2 C16.2 C17.2 C24.2 J2.2 R18.1 T1.7 TP4.1 U3.5
  other v1: 2135,105 3335,245 3385,360 3385,450 3385,540 3335,645 3260,1140 3350,1140 3245,1400
  other v2: 2575,245 2635,245 2725,905 2725,1045 2725,1255 2725,1395 2115,1685 2116.26,1735
NetC1_2: C1.2 C5.1 C6.1 C7.1 C8.1 L1.2 R1.2 R4.2 R8.2 T1.5 T1.6 | length 2489.7
  Top Layer w6: v2(800,1395) 800,1356.06 R8.2@801.06,1355
  Top Layer w16: v2(800,1395) 850,1445 1485,1445 1595,1335 1595,478.78 T1.5
  Bottom Layer w20: v2(800,1395) 800,1330 850,1280 850,960 v2(900,910)
NetC3_1: C3.1 C4.1 J1.2 L1.1 TP1.1
NetC8_2: C8.2 D1.1 R1.1
NetC9_1: C9.1 C11.1 C12.1 C15.1 C16.1 D2.4 L2.1 R3.1
NetC9_2: C9.2 R2.2
NetC10_1: C10.1 C13.1 C14.1 C17.1 J2.1 L2.2 R3.2 R7.2 TP3.1 | length 1452.9
  Top Layer w10: R7.2 2493.5,1393.5 2545,1445 3265,1445 3555,1155 3555,1045 J2.1
NetC18_1: C18.1 R6.1 U1.1 | length 406.8
  Top Layer w10: U1.1 795.71,1185.71 905,1295 1045.94,1295 C18.1
NetC19_1: C19.1 D7.1 D8.3 R4.1 U1.10 | length 766.7
  Top Layer w10: U1.10 R4.1@815.71,1024.29 ; R4.1@835,1045.63 924.37,1135 ; C19.1 920,1139.37 924.37,1135 ; D7.1 1287.76,1305 D8.3 924.37,1135
NetC20_1: C20.1 C21.1 R14.1 R18.2 U3.4 | length 276.7
  Top Layer w10: R18.2 2400.44,1655.95 U3.4 2389.1,1576.93 C20.1 2452.52,1573.5 2454.96,1571.06 2456.5,1571.06 R14.1
NetC20_2: C20.2 D6.1 R13.1 R15.2 U2.2 U3.3 | length 677.8
  Top Layer w10: U2.2 2075,1412.48 2075,1575 2127.72,1627.72 D6.1 ; D6.1@2131.42,1644.61 U3.3 2334.96,1590.47 R13.1
NetC21_2: C21.2 R15.1 | length 60
  Top Layer w10: R15.1 C21.2@2452.52,1513.5
NetC22_1: C22.1 R19.1 | length 41
  Top Layer w10: R19.1 C22.1
NetC23_1: C23.1 R10.1 U1.9 | length 188.4
  Top Layer w10: U1.9 724.69,985.53 734.53,975.69 C23.1 R10.1@734.53,840
NetC24_1: C24.1 D5.1 D6.3 R12.1 | length 355.3
  Top Layer w10: D5.1 2170.91,1510.91 v1(2225,1565) ; C24.1 2225,1717.56 v3(2225,1675) ; D6.3@2225,1600.71 v1(2225,1565) ; R12.1@2268.9,1565 v1(2225,1565)
  Bottom Layer w10: v1(2225,1565) v3(2225,1675)
NetD1_2: D1.2 Q1.5 Q1.6 Q1.7 Q1.8 T1.3 T1.4
NetD2_1: D2.1 D2.3 R2.1 T1.8 | length 393.3
  Top Layer w10: T1.8 2735.16,478.78 D2.3@2735.16,311.22 ; R2.1@2741.14,214.37 D2.3
NetD3_1: D3.1 Q2.1 R5.2
NetD3_3: D3.3 Q1.4 Q2.2
  other v2: 680,550 1080,550
NetD4_1: D4.1 R7.1 R14.2 | length 224.5
  Top Layer w10: D4.1@2397.41,1321.26 R7.1 2397.41,1417.41 2447.44,1467.44 R14.2
NetD4_2: D4.2 D5.3 R11.2 R12.2 R13.2 | length 372.4
  Top Layer w10: R11.2 D4.2 2304.77,1365.75 R13.2 2299.77,1395.95 D5.3 2232.52,1473.5 R12.2
NetD8_1: D8.1 T1.1 | length 166.3
  Top Layer w10: D8.1 T1.1@1378.58,1097.6
NetQ1_1: Q1.1 Q1.2 Q1.3 R6.2 R9.2 | length 583.6
  Top Layer w10: v1(1100,1260) 1100,1293.94 R6.2@1101.06,1295
  Bottom Layer w10: v1(1030,745) 1025,750 1025,1095 1100,1170 v1(1100,1260)
NetR5_1: R5.1 U1.8 | length 290.3
  Top Layer w6: R5.1 702.56,777.56 v2(705,780)
  Top Layer w10: v2(705,960) U1.8
  Bottom Layer w6: v2(705,780) v2(705,960)
NetR8_1: R8.1 R17.2 U1.2 | length 178.1
  Top Layer w10: U1.2 724.69,1225.69 745.94,1246.95 745.94,1295 R8.1@745.94,1355
NetR10_2: R10.2 R19.2 U1.3 U2.4 | length 2247.9
  Top Layer w10: R10.2@665,855 605,855 565,895 565,1005 605,1045 605,1195 656,1246 ; U1.3 705,1226 685,1246 656,1246 ; U2.4 1884.5,1318.5 1915,1349 1915,1395 1805,1505 765,1505 645,1385 R19.2 628.69,1342.69 616,1330 616,1286 656,1246
NetR11_1: R11.1 U2.1 | length 63.4
  Top Layer w10: U2.1 R11.1@2182.41,1318.5
NetR16_1: R16.1 U1.6 | length 95.7
  Top Layer w10: R16.1 605,1015 614.29,1024.29 U1.6@664.41,1024.29
PGND: C2.2 C3.2 C4.2 C5.2 C6.2 C7.2 C18.2 C19.2 C22.2 C23.2 D7.2 J1.1 Q2.3 R9.1 R16.2 R17.1 T1.2 TP2.1 U1.4 U1.5 U1.7 U2.3 | length 364.7
  Top Layer w10: v1(605,895) R16.2 C23.2@657.44,927.44 ; C23.2 675.47,975.47 685.32,985.32 U1.7 U1.4
  other v1: 1390,50 1790,50 1390,225 810,625 855,625 900,625 635,670 965,680 540,715 855,725 595,795 815,875 1285,955 1285,1025 545,1075 800,1080 800,1150 640,1190 545,1230 790,1245 1555,1305 1145,1355 695,1385 930,1400 1825,1405
  other v3: 1895,1595
pads on no net: D3.2 D5.2 D6.2 D8.2 T1.9 T1.10 T1.11 T1.12 U3.1 U3.2

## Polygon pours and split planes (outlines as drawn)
PGND on Top Layer "TOP_LAYER_PGND_P000" (solid, remove dead copper, pour order 0): 25,1775 1975,1775 1975,25 25,25
GND on Top Layer "TOP_LAYER_GND_P004" (solid, remove dead copper, pour order 4): 2005,25 2005,1775 3675,1775 3675,25
GND on Bottom Layer "BOTTOM_LAYER_GND_P006" (solid, remove dead copper, pour order 6): 2005,1775 3675,1775 3675,25 2005,25
PGND on Bottom Layer "BOTTOM_LAYER_PGND_P002" (solid, remove dead copper, pour order 2): 25,1775 1975,1775 1975,25 25,25

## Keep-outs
Keep-Out Layer:
  lines w10: -5,0 ccw(c0,0) 0,-5 ; -5,0 ccw(c0,0) 0,-5 ; -5,0 -5,1800 ; -5,1800 cw(c0,1800) 0,1805 ; -5,1800 cw(c0,1800) 0,1805 ; 0,-5 3700,-5 ; 0,1805 3700,1805 ; 3700,-5 ccw(c3700,0) 3705,0 ; 3700,-5 ccw(c3700,0) 3705,0 ; 3700,1805 cw(c3700,1800) 3705,1800 ; 3700,1805 cw(c3700,1800) 3705,1800 ; 3705,0 3705,1800
  text ".Layer_Name" at 577,-858.49 h60

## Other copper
Top Layer:
  rectangle net NetD3_3: 1045,535.2 1110,600
  rectangle net NetD3_3: 620,535 744.38,600
  region net NetC3_1: 125,305 285,305 285,1365 515,1365 515,1495 125,1495
  region net NetD3_1: 605,565 575,565 575,745 775,745 775,655 745,655 745,705 625,705 595,705 595,595 605,595
  region net NetC8_2: 1105,785 955,785 955,905 1045,905 1045,1050 1135,1050 1135,925 1105,925
  region net NetC1_2: 800,925 800,985 880,985 880,1052.07 955,1052.07 955,925 927.2,925 927.2,855 880,855 880,925
  region net NetQ1_1: 925,775 925,705 1045,705 1045,610 1110,610 1110,775
  region net NetD2_1: 2525,535 2805,535 2805,95 2675,95 2675,425 2525,425
  region net NetC9_2: 3075,255 2895,255 2895,95 3075,95
  region net NetC10_1: 2875,705 3555,705 3555,1045 3145,1045 3145,1365 2985,1365 2985,835 2875,835
  region net NetC9_1: 2875,695 3270,695 3270,125 3085,125 3085,275 2875,275
  region net NetD1_2: 1175,910 1275,910 1275,845 1450,845 1450,535 1125,535 1125,765 1175,765
  region net NetC1_2: 1975,25 1865,25 1625,265 495,265 495,525 1975,525
  text ".Layer_Name" at 577,-858.49 h60
Bottom Layer:
  rectangle net NetD3_3: 663.78,533.78 1096.22,566.22
  text ".Layer_Name" at 577,-858.49 h60

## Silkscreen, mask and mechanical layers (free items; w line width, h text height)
Top Overlay:
  region: 1250,140 950,140 950,40 1250,40
  text "PMP21030_RevA-" at 150,60 h108.27
  text ".Layer_Name" at 577,-858.49 h60
Bottom Overlay:
  text ".Layer_Name" at 577,-858.49 h60
Top Paste:
  text ".Layer_Name" at 577,-858.49 h60
Bottom Paste:
  text ".Layer_Name" at 577,-858.49 h60
Top Solder:
  text ".Layer_Name" at 577,-858.49 h60
  text ".Layer_Name" at 577,-858.49 h60
Bottom Solder:
  text ".Layer_Name" at 577,-858.49 h60
Drill Guide:
  text ".Layer_Name" at 577,-858.49 h60
M1 Board Outline:
  the board outline again, w10
  text ".Layer_Name" at 577,-858.49 h60
M2 Board Dimensions:
  rectangle: 125,-400 500,-275
  rectangle: 0,-275 125,-150
  lines w7: 0,-275 1000,-275 ; 125,-400 125,-150 ; 250,-400 250,-150 ; 500,-400 500,-150 ; 750,-400 750,-150 ; 0,-400 0,-150 1000,-150 1000,-400 0,-400
  text ".Layer_Name" at 577,-858.49 h60
M3 3D STEP Top:
  text ".Layer_Name" at 577,-858.49 h60
M4 3D STEP Bottom:
  text ".Layer_Name" at 577,-858.49 h60
M5 Assembly Top:
  lines w10: -292,-930.17 6308,-930.17 ; -292,-726.83 6310,-726.83 ; -292,-523.5 -292,-1133.5 3713,-1133.5 6310,-1133.5 6310,-523.5 -291.5,-523.5 -291.5,-1133.5 1284,-1133.5 ; 2173,-1133.5 2173,-523.5 ; 3440,-726.83 3440,-523.5 ; 4280,-726.83 4280,-523.5 ; 4902,-1140 4902,-937.17
  text "COMPONENTS MARKED 'DNP' SHOULD NOT BE POPULATED." at 1153.5,-318.5 h60
  text "ASSEMBLY VARIANT:" at 1153,-434 h60
  text ".VariantName" at 2189,-434 h60
  text "PCB VIEWED FROM TOP SIDE" at -228.5,-655.67 h60
  text "BOARD #:" at 2248,-655.67 h60
  text ".PRJ_Number" at 2793.5,-655.67 h60
  text "REV:" at 3638,-655.67 h60
  text ".PCB_Rev" at 3929.5,-655.67 h60
  text "SVN REV:" at 4476,-655.67 h60
  text ".VersionControl_RevNumber" at 4982,-655.67 h60
  text "TID #:" at 2248,-859 h60
  text ".TID" at 2793.5,-859 h60
  text "PLOT NAME =" at -228.5,-1064.34 h60
  text ".plot_File_Name" at 577,-1064.34 h60
  text "GENERATED    :" at 2250,-1064.34 h60
  text ".Print_Date" at 3119.5,-1064.34 h60
  text ".Print_Time" at 3848.5,-1064.34 h60
  text "TEXAS INSTRUMENTS" at 5113,-1064.34 h60
M6 Assembly Bottom:
  lines w10: -292.5,-727.33 6309.5,-727.33 ; -290.5,-930.67 6309.5,-930.67 ; 1115.5,-1140.5 1115.5,-937.67 ; 1737.5,-727.33 1737.5,-524 ; 2577.5,-727.33 2577.5,-524 ; 3844.5,-1134 3844.5,-524 ; 4733.5,-1134 6309,-1134 6309,-524 -292.5,-524 -292.5,-1134 2304.5,-1134 6309.5,-1134 6309.5,-524
  text "COMPONENTS MARKED 'DNP' SHOULD NOT BE POPULATED." at 6102,-318 h60
  text ".VariantName" at 5058,-434 h60
  text "ASSEMBLY VARIANT:" at 6097,-434 h60
  text ".VersionControl_RevNumber" at 1035.5,-656.17 h60
  text "SVN REV:" at 1541.5,-656.17 h60
  text ".PCB_Rev" at 2088,-656.17 h60
  text "REV:" at 2379.5,-656.17 h60
  text ".PRJ_Number" at 3224,-656.17 h60
  text "BOARD #:" at 3769.5,-656.17 h60
  text "PCB VIEWED FROM BOTTOM SIDE" at 6246,-656.17 h60
  text ".TID" at 3224,-859.5 h60
  text "TID #:" at 3769.5,-859.5 h60
  text "TEXAS INSTRUMENTS" at 904.5,-1064.84 h60
  text ".Print_Time" at 2169,-1064.84 h60
  text ".Print_Date" at 2898,-1064.84 h60
  text "GENERATED    :" at 3767.5,-1064.84 h60
  text ".plot_File_Name" at 5440.5,-1064.84 h60
  text "PLOT NAME =" at 6246,-1064.84 h60
M9 Title Sheet:
  drawing of 57 lines, arcs and shapes, not listed
  text "1" at 739.84,8036.5 h70
  text "2" at 3235.5,8036.5 h70
  text "3" at 5724.84,8036.5 h70
  text "4" at 8231.51,8036.5 h70
  text "5" at 10730.5,8036.5 h70
  text "6" at 13235.5,8036.5 h70
  text "A" at -416.5,6893.5 h70
  text "A" at 14383.5,6893.5 h70
  text "B" at -416.5,4513.5 h70
  text "B" at 14383.5,4513.5 h70
  text "C" at -416.5,2138.5 h70
  text "C" at 14383.5,2138.5 h70
  text "PROJECT TITLE:" at 11343.5,277.5 h45
  text ".PRJ_Title" at 11393.5,144.17 h70
  text "DESIGNED FOR:" at 11343.5,-23.5 h45
  text ".PRJ_Customer" at 11393.5,-163.5 h70
  text "D" at -416.5,-231.5 h70
  text "D" at 14383.5,-231.5 h70
  text "FILE NAME:" at 11343.5,-323.5 h45
  text ".PCB_File_Name_No_Path" at 11393.5,-443.5 h70
  text "Texas Instruments (TI) and/or its licensors do not warrant the accuracy or completeness of this specification" at 6374,-605.34 h45
  text "ENGINEER:" at 11343.5,-613.5 h45
  text "LAYOUT BY:" at 12848.5,-613.5 h45
  text "or any information contained therein. TI and/or its licensors do not warrant that this design will meet" at 6329.01,-718 h45
  text ".PRJ_Engineer" at 11393.5,-768.49 h70
  text ".PCB_Layout" at 12899,-768.49 h70
  text "the specifications, will be suitable for your application or fit for any particular purpose, or will operate in" at 6329.01,-830.67 h45
  text ".Layer_Name" at 577,-858.49 h60
  text "ALTIUM DESIGNER VERSION:" at 12848.5,-923.5 h45
  text "an implementation. TI and/or its licensors do not warrant that the design is production worthy. You should" at 6329.01,-943.33 h45
  text "completely validate and test your design implementation to confirm the system functionality for your application." at 6374,-1056 h45
  text ".print_Scale" at 11393.5,-1056.83 h70
  text ".Application_BuildNumber" at 12899,-1056.83 h70
  text "1" at 739.84,-1263.5 h70
  text "2" at 3235.5,-1263.5 h70
  text "3" at 5724.84,-1263.5 h70
  text "4" at 8231.51,-1263.5 h70
  text "5" at 10730.5,-1263.5 h70
  text "6" at 13235.5,-1263.5 h70
M10 Fab Notes:
  drawing of 173 lines, arcs and shapes, not listed
  text "DESIGN INFORMATION" at 12378.02,6201 h60
  text "MIN. TRACK WIDTH:" at 11733.46,6021 h60
  text "8" at 12829.7,6021 h60
  text "MIL" at 12984.46,6021 h60
  text "MIN. CLEARANCE:" at 11733.46,5889 h60
  text "0.2" at 12769.7,5889 h60
  text "mm" at 12984.46,5889 h60
  text "MIN. VIA PAD SIZE:" at 11733.46,5757 h60
  text "24" at 12799.71,5757 h60
  text "MIL" at 12984.46,5757 h60
  text "0.05mm (2MIL)" at 12428.46,5615.29 h60
  text "MINIMUM ANNULAR RING" at 11404.23,5611 h60
  text "EXTERNAL" at 13136.46,5611 h60
  text "PER" at 11604.23,5493 h60
  text "IPC-D-275 CLASS 2 LEVEL C" at 11824.23,5493 h60
  text "MIL, HOLES" at 13312.46,5380.71 h60
  text "+/-" at 12920,5380 h60
  text "+/-" at 13774,5380 h60
  text "REGISTRATION TOLERANCES:" at 11404.23,5375 h60
  text "METAL" at 12604,5375 h60
  text "5" at 13180.2,5375 h60
  text "3" at 14013.2,5375 h60
  text "MIL" at 14129.46,5375 h60
  text "+/-" at 13774,5262 h60
  text "HOLE SIZE TOLERANCE (UNLESS OTHERWISE SPECIFIED):" at 11404.23,5257 h60
  text "3" at 14013.2,5257 h60
  text "MIL" at 14129.46,5257 h60
  text "MATERIAL:" at 11329.46,5047.54 h60
  text "FR-4 High Tg" at 12315.9,4907.21 h60
  text "FR-408" at 11750.46,4898.64 h60
  text "OTHER" at 13238.46,4898.64 h60
  text "X" at 12161,4895 h60
  text "62 MIL (1.6mm) +/-10%" at 12070.56,4735.92 h60
  text "THICKNESS:" at 11404.23,4731.64 h60
  text "X" at 11942.4,4731.64 h60
  text "OTHER" at 13355.46,4731.64 h60
  text "TOLERANCE:" at 11404.23,4573.64 h60
  text "X" at 12243.53,4573.64 h60
  text "ANSI IPC-6012 TYPE 3 CLASS 2" at 12430.48,4573.64 h60
  text "OTHER +/-" at 12430.46,4417.64 h60
  text "BOW & TWIST:" at 11404.23,4260.64 h60
  text "X" at 12243.53,4260.64 h60
  text "ANSI IPC-6012 TYPE 3 CLASS 2" at 12430.48,4260.64 h60
  text "OTHER +/-" at 12430.46,4102.13 h60
  text "DRILLING:" at 11329.46,3963.64 h60
  text "REFERENCE:" at 11404.23,3846.64 h60
  text "X" at 12052.46,3846.64 h60
  text "AS SHOWN" at 12239.46,3846.64 h60
  text "X" at 12953.46,3846.64 h60
  text "NC_DRILL FILES" at 13090.46,3846.64 h60
  text "PTH COPPER THICKNESS:" at 11404.23,3688.64 h60
  text "X" at 12534.46,3688.64 h60
  text "20-30 um" at 12671.46,3688.64 h60
  text "OTHER" at 13388.46,3688.64 h60
  text "BOARD FINISH:" at 11329.46,3529.64 h60
  text "SILKSCREEN:" at 11484.68,3411.64 h60
  text "X" at 12433.46,3411.64 h60
  text "TOP" at 12559.46,3411.64 h60
  text "X" at 12943.46,3411.64 h60
  text "BOTTOM" at 13070.46,3411.64 h60
  text "SILKSCREEN COLOR:" at 11484.68,3244.64 h60
  text "X" at 12432.42,3244.64 h60
  text "WHITE" at 12559.46,3244.64 h60
  text "OTHER" at 13070.46,3244.64 h60
  text "X" at 12563.42,3085.44 h60
  text "GREEN" at 12690.46,3085.44 h60
  text "OTHER" at 13308.46,3085.44 h60
  text "SOLDER RESIST COLOR:" at 11484.68,3074.64 h60
  text "X" at 12563.42,2915.44 h60
  text "MATTE" at 12690.46,2915.44 h60
  text "SEMI-GLOSS" at 13308,2914.8 h60
  text "IMMERSION GOLD (ENIG)" at 12390.46,2726.92 h60
  text "ENEPIG" at 13728,2723.64 h60
  text "SURFACE FINISH:" at 11329.46,2722.64 h60
  text "X" at 12203.51,2722.64 h60
  text "IMM. TIN/SILVER OR EQUIV" at 11659,2565.64 h60
  text "OTHER" at 13090.46,2565.64 h60
  text "ARRAY/PANEL:" at 11329.46,2386.64 h60
  text "CUT AND TRIM PER M1 BOARD OUTLINE" at 12390.46,2382.35 h60
  text "N.C. ROUTE" at 12390.46,2230.64 h60
  text "X" at 13069.46,2230.64 h60
  text "V. SCORE" at 13256.46,2230.64 h60
  text "CERTIFICATION:" at 11329.46,2093.64 h60
  text "MATERIALS AND WORKMANSHIP FOR ALL PCBS" at 12054.46,2093.64 h60
  text "TO MEET OR EXCEED THE REQUIREMENTS OF:" at 12054.46,1995.64 h60
  text "X" at 11680.96,1859.13 h60
  text "ANSI IPC-A-600F CLASS ->" at 11819.96,1859.13 h60
  text "X" at 13459.02,1859.13 h60
  text "2" at 13577.96,1859.14 h60
  text "1" at 13262.96,1857.64 h60
  text "3" at 13931.96,1857.64 h60
  text "X" at 12495.02,1699.64 h60
  text "RoHS" at 12631.96,1699.64 h60
  text "OTHER" at 13276.36,1699.64 h60
  text "PER ORDER" at 13673.42,1699.64 h60
  text "ALL BOARDS MUST MEET OR EXCEED UL94-V0 REQUIREMENTS." at 11357,1534 h60
  text "PCB MUST BEAR THE UL94V-0 UL REGISTERED MATERIAL ID NUMBER" at 11357,1414 h60
  text "ADDITIONAL REQUIREMENTS:" at 11329.46,1240.64 h60
  text "MICROSECTION:" at 11404.23,1125.64 h60
  text "YES" at 12309.96,1125.64 h60
  text "REQUIRED" at 13171.46,969.49 h60
  text "BARE BOARD ELEC. TEST:" at 11404.23,966.64 h60
  text "NONE" at 12709.96,966.64 h60
  text "PER ORDER" at 13763.46,966.64 h60
  text "X" at 12585,965 h60
  text ".Layer_Name" at 577,-858.49 h60
M11 Gerber Information:
  lines w10: -292,-930.17 6308,-930.17 ; -292,-726.83 6310,-726.83 ; -292,-523.5 -292,-1133.5 3713,-1133.5 6310,-1133.5 6310,-523.5 -291.5,-523.5 -291.5,-1133.5 1284,-1133.5 ; 2173,-1133.5 2173,-523.5 ; 3440,-726.83 3440,-523.5 ; 4280,-726.83 4280,-523.5 ; 4902,-1140 4902,-937.17
  text "ALL ARTWORK VIEWED FROM TOP SIDE" at -228.5,-655.67 h60
  text "BOARD #:" at 2248,-655.67 h60
  text ".PRJ_Number" at 2793.5,-655.67 h60
  text "REV:" at 3638,-655.67 h60
  text ".PCB_Rev" at 3929.5,-655.67 h60
  text "SVN REV:" at 4476,-655.67 h60
  text ".VersionControl_RevNumber" at 4982,-655.67 h60
  text "LAYER NAME =" at -228.5,-858.49 h60
  text "TID #:" at 2248,-859 h60
  text ".TID" at 2793.5,-859 h60
  text "PLOT NAME =" at -228.5,-1064.34 h60
  text ".plot_File_Name" at 577,-1064.34 h60
  text "GENERATED    :" at 2250,-1064.34 h60
  text ".Print_Date" at 3119.5,-1064.34 h60
  text ".Print_Time" at 3848.5,-1064.34 h60
  text "TEXAS INSTRUMENTS" at 5113,-1064.34 h60
M12 Stackup:
  drawing of 191 lines, arcs and shapes, not listed
  text "Layer" at 9662.5,7347.5 h60
  text "Name" at 10072.41,7347.5 h60
  text "Material" at 11002.16,7347.5 h60
  text "Thickness" at 11861.92,7347.5 h60
  text "Constant" at 12511.76,7347.5 h60
  text "Board Layer Stack" at 13081.62,7347.5 h60
  text "1" at 9662.5,7227.5 h60
  text "Top Overlay" at 10072.41,7227.5 h60
  text "2" at 9662.5,7107.5 h60
  text "Top Solder" at 10072.41,7107.5 h60
  text "Solder Resist" at 11002.16,7107.5 h60
  text "0.40mil" at 11861.92,7107.5 h60
  text "3.5" at 12511.76,7107.5 h60
  text "3" at 9662.5,6987.5 h60
  text "Top Layer" at 10072.41,6987.5 h60
  text "Copper" at 11002.16,6987.5 h60
  text "1.40mil" at 11861.92,6987.5 h60
  text "4" at 9662.5,6867.5 h60
  text "Dielectric1" at 10072.41,6867.5 h60
  text "FR-4" at 11002.16,6867.5 h60
  text "59.20mil" at 11861.92,6867.5 h60
  text "4.8" at 12511.76,6867.5 h60
  text "5" at 9662.5,6747.5 h60
  text "Bottom Layer" at 10072.41,6747.5 h60
  text "Copper" at 11002.16,6747.5 h60
  text "1.40mil" at 11861.92,6747.5 h60
  text "6" at 9662.5,6627.5 h60
  text "Bottom Solder" at 10072.41,6627.5 h60
  text "Solder Resist" at 11002.16,6627.5 h60
  text "0.40mil" at 11861.92,6627.5 h60
  text "3.5" at 12511.76,6627.5 h60
  text "7" at 9662.5,6507.5 h60
  text "Bottom Overlay" at 10072.41,6507.5 h60
  text ".Layer_Name" at 577,-858.49 h60
M13 Component Bodies Top:
  text ".Layer_Name" at 577,-858.49 h60
M14 Component Bodies Bottom:
  text ".Layer_Name" at 577,-858.49 h60
M15 Courtyards Top:
  text ".Layer_Name" at 577,-858.49 h60
M16 Courtyards Bottom:
  text ".Layer_Name" at 577,-858.49 h60
Drill Drawing:
  lines w10: 4001.09,150.19 4014.9,150.19 4014.9,136.38 4042.53,136.38 4042.53,150.19 4056.34,150.19 4056.34,177.82 4042.53,177.82 4042.53,191.63 4014.9,191.63 4014.9,177.82 4001.09,177.82 4001.09,150.19 ; 4001.09,260.7 4056.34,260.7 4056.34,315.95 4001.09,315.95 4001.09,260.7 ; 4001.09,440.27 4056.34,440.27 4028.72,385.02 4001.09,440.27 ; 4001.09,523.15 4014.9,523.15 4028.72,509.34 4042.53,523.15 4056.34,523.15 4042.53,536.96 4056.34,550.78 4042.53,550.78 4028.72,564.59 4014.9,550.78 4001.09,550.78 4014.9,536.96 4001.09,523.15 ; 4001.09,633.66 4028.72,647.47 4056.34,633.66 4042.53,661.28 4056.34,688.91 4028.72,675.1 4001.09,688.91 4014.9,661.28 4001.09,633.66
  lines w12: 3951,99.08 7182.49,99.08 ; 3951,720.68 7182.49,720.68 ; 4288.86,-25.24 4288.86,845 ; 4620.86,-25.24 4620.86,845 ; 5257.43,-25.24 5257.43,845 ; 5516.57,-25.24 5516.57,845 ; 5891.72,-25.24 5891.72,845 ; 6616.05,-25.24 6616.05,845 ; 3951,-25.24 7182.49,-25.24 7182.49,845 3951,845 3951,-25.24
  text "Symbol" at 4025.59,757.98 h72
  text "Quantity" at 4326.16,757.98 h72
  text "Finished Hole Size" at 4658.16,757.98 h72
  text "Plated" at 5294.72,757.98 h72
  text "Hole Type" at 5553.86,757.98 h72
  text "Drill Layer Pair" at 5929.02,757.98 h72
  text "Hole Tolerance" at 6653.35,757.98 h72
  text "14" at 4326.16,633.66 h60
  text "10.00mil (0.254mm)" at 4658.16,633.66 h60
  text "PTH" at 5294.72,633.66 h60
  text "Round" at 5553.86,633.66 h60
  text "Top Layer - Bottom Layer" at 5929.02,633.66 h60
  text "40" at 4326.16,509.34 h60
  text "12.00mil (0.305mm)" at 4658.16,509.34 h60
  text "PTH" at 5294.72,509.34 h60
  text "Round" at 5553.86,509.34 h60
  text "Top Layer - Bottom Layer" at 5929.02,509.34 h60
  text "2" at 4326.16,385.02 h60
  text "29.53mil (0.750mm)" at 4658.16,385.02 h60
  text "PTH" at 5294.72,385.02 h60
  text "Round" at 5553.86,385.02 h60
  text "Top Layer - Bottom Layer" at 5929.02,385.02 h60
  text "4" at 4326.16,260.7 h60
  text "50.00mil (1.270mm)" at 4658.16,260.7 h60
  text "PTH" at 5294.72,260.7 h60
  text "Round" at 5553.86,260.7 h60
  text "Top Layer - Bottom Layer" at 5929.02,260.7 h60
  text "4" at 4326.16,136.38 h60
  text "63.00mil (1.600mm)" at 4658.16,136.38 h60
  text "PTH" at 5294.72,136.38 h60
  text "Round" at 5553.86,136.38 h60
  text "Top Layer - Bottom Layer" at 5929.02,136.38 h60
  text "64 Total" at 4326.16,12.06 h60
  text ".Layer_Name" at 577,-858.49 h60
M17 Embedded Cavity:
  text ".Layer_Name" at 577,-858.49 h60
M18 Embedded Assembly:
  text ".Layer_Name" at 577,-858.49 h60
M19 Embedded Keepout:
  text ".Layer_Name" at 577,-858.49 h60

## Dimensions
0,0 to 3700,0 on M2 Board Dimensions
0,0 to 0,1800 on M2 Board Dimensions
0,-400 to 1000,-400 on M2 Board Dimensions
